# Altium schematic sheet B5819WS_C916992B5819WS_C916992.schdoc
size 127 x 101 mm
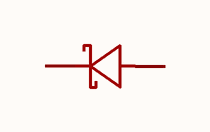
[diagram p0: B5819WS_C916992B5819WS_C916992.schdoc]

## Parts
D?  b5819ws_c916992  [SOD-323_L1.7-W1.3-LS2.5-RD]  (value not drawn)

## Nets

Not connected (* = marked no-connect by the designer): D? 1(K) 2(A)

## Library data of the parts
D? = b5819ws_c916992: 二极管配置:独立式;正向压降(Vf):600mV@1A;直流反向耐压(Vr):40V;整流电流:1A;; Manufacturer: JSMSEMI(杰盛微); AddInBom: yes; ModelId: 0f2f330c645944df9245ac3c3fec3456; ModelName: SOD-323_L1.7-W1.3-LS2.5-FD; ModelTransform: 98.425,49.2125,0,0,0,0,0,0,0; Diode Configuration: 独立式; Voltage - DC Reverse(Vr): 40V; Current - Rectified: 1A; Reverse Leakage Current (Ir): 1mA@40V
